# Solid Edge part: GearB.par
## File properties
Author: Chalangana Oshan
Template: iso metric part.par
Last saved by: Nimesh.N
Revision: 18
Application: Solid Edge
Density: 7250.000 kg/m^3
Accuracy: 0.990
Username: Nimesh.N
Material: Iron:0.6025 , EN-GJL-250
Face Style: Gray
Fill Style: ANSI31(Iron)
Grouping: Iron\Gray Cast Iron
LibraryName: Materials-DIN
Coef. of Thermal Exp: 1.05e-05
Thermal Conductivity: 58.0
Specific Heat: 460.0
Modulus of Elasticity: 120000003072.0
Poisson's Ratio: 0.26
Yield Stress: 165593984.0
Ultimate Stress: 250000000.0
Elongation: 0.0
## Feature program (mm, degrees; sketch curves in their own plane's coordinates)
sketch for "unnamed Protrusion 1" plane through (0, 0, 0) normal (0, 0, 1) x-axis (1, 0, 0)
  circle centre (0, 0) radius 90
extrude "unnamed Protrusion 1" add finite 130 along -normal
sketch used by "unnamed Cutout 1" plane through (0, 0, 0) normal (0, 0, 1) x-axis (1, 0, 0)
  line (0, 0) -> (-17.5581, 88.2707)
  line (0, 0) -> (-14.6606, 88.7979)
  line (0, 0) -> (-15.6283, 88.6327)
  line (-3.3121, 67.4187) -> (3.3121, 67.4187)
  arc centre (-60.8934, 50.5549) radius 60 from (-14.6606, 88.7979) to (-3.3121, 67.4187) cw
  arc centre (60.8934, 50.5549) radius 60 from (14.6606, 88.7979) to (3.3121, 67.4187) ccw
extrude "unnamed Cutout 1" cut through along -normal
pattern "unnamed Pattern 1" of "unnamed Cutout 1"
pattern "unnamed Pattern 2"
sketch for "unnamed Cutout 2" plane through (0, 0, 0) normal (0, 0, 1) x-axis (0.707107, 0.707107, 0)
extrude "unnamed Cutout 2" cut through along -normal
sketch for "unnamed Cutout 3" plane through (0, 0, 0) normal (0, 0, 1) x-axis (0.707107, 0.707107, 0)
extrude "unnamed Cutout 3" cut through along -normal
Other named dimensions: "ExtrudedSurface_3": FiniteDepth = 130 mm
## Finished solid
Body 1: sheet body, 1 face, 2 edges, 0 vertices.
  Faces by surface: cylinder 1
  Edges by curve: circle 2
Body 2: solid body, 70 faces, 204 edges, 136 vertices.
  Faces by surface: cylinder 49, plane 21
  Edges by curve: line 106, circle 98
Bounding box of the edges (mm): 177.596 x 177.596 x 130.000, from (-88.7979, -88.7979, -130) to (88.7979, 88.7979, 0).
Cylindrical faces by radius (mm): R36.03 x1, R60 x32, R80 x1, R90 x16
Planar faces by outward normal: +x 1, +y 1, +z 1, -x 1, -y 1, -z 1, oblique 15
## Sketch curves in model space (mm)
line (0, 0, 0) -> (-15.6283, 88.6327, 0)
line (0, 0, 0) -> (-17.5581, 88.2707, 0)
line (0, 0, 0) -> (4.4161, 89.8916, 0)
line (0, 0, 0) -> (-4.4161, 89.8916, 0)
arc centre (60.8934, 50.5549, 0) radius 60 from (14.6606, 88.7979, 0) through (7.8971, 78.6865, 0) to (3.3121, 67.4187, 0)
line (-3.3121, 67.4187, 0) -> (3.3121, 67.4187, 0)
arc centre (-60.8934, 50.5549, 0) radius 60 from (-14.6606, 88.7979, 0) through (-7.8971, 78.6865, 0) to (-3.3121, 67.4187, 0)
line (0, 0, 0) -> (-14.6606, 88.7979, 0)
circle centre (0, 0, 0) radius 90
circle centre (0, 0, 0) radius 80
circle centre (0, 0, 0) radius 67.5
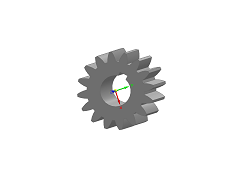
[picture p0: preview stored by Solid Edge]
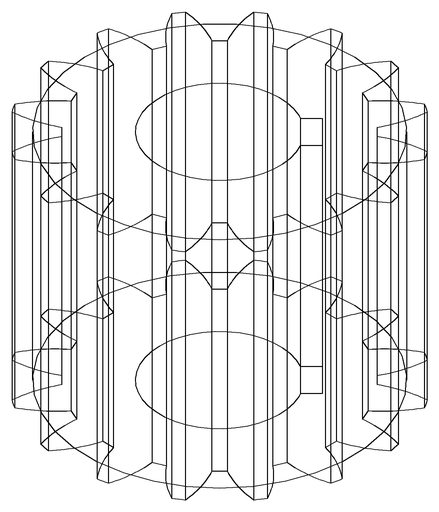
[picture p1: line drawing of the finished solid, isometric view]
